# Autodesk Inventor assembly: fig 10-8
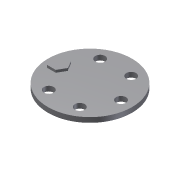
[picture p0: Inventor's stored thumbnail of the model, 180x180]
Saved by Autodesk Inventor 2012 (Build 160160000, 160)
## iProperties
Created: 2008-05
Part Number: fig 10-8
Document SubType Name: Assembly
Designer: CADCIM
Author: CADCIM
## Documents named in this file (3)
- C:\Users\CadCim\Documents\SAILESH\inventor-2011-fact-prt\c10-inv-2011-prt\c10_inv_2012_prt\fig 10-8.iam
- C:\Users\CadCim\Documents\SAILESH\inventor-2011-fact-prt\c10-inv-2011-prt\c10_inv_2012_prt\Part4.ipt
- C:\Users\CadCim\Documents\SAILESH\inventor-2011-fact-prt\c10-inv-2011-prt\c10_inv_2012_prt\Part5.ipt
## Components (2 placed, 2 different names)
1. Part4:1
2. Part5:1
